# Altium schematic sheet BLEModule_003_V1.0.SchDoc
size 152 x 127 mm; SheetNumber: 0; SheetTotal: 0
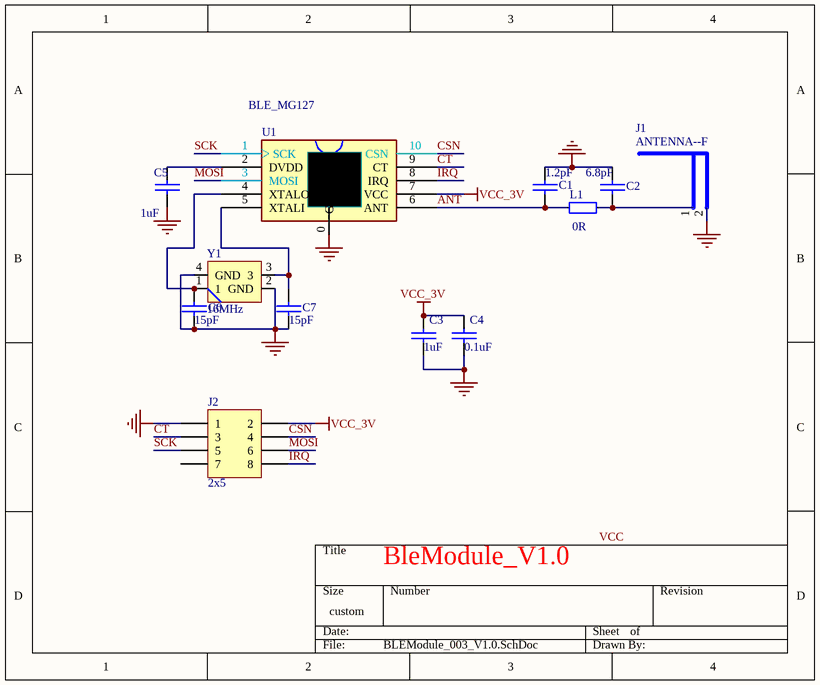
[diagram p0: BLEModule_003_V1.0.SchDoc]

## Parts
C1  1.2pF  [0402C]
C2  6.8pF  [0402C]
C3  1uF  [0402C]
C4  0.1uF  [0402C]
C5  1uF  [0402C]
C6  15pF  [0402C]
C7  15pF  [0402C]
J1  ANTENNA--F  [PIFA_LARGE]
J2  2x5  [HDR2X4]
L1  value 0R  [0402]  (hidden comment: 3.6nF)
U1  BLE_MG127  [DFN10]
Y1  16MHz  [XT3225]

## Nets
GND: C1.1 C2.1 C3.2 C4.2 C5.2 C6.2 C7.2 J1.2 J2.1 U1.0(GND) Y1.2(GND) Y1.4(GND)
VCC_3V: C3.1 C4.1 J2.2 U1.7(VCC)
ANT: C1.2 L1.2 U1.6(ANT)
CSN: J2.4 U1.10(CSN)
CT: J2.3 U1.9(CT)
IRQ: J2.8 U1.8(IRQ)
MOSI: J2.6 U1.3(MOSI)
SCK: J2.5 U1.1(SCK)
NetC2_2: C2.2 J1.1 L1.1
NetC5_1: C5.1 U1.2(DVDD)
NetC6_1: C6.1 U1.4(XTALO) Y1.1
NetC7_1: C7.1 U1.5(XTALI) Y1.3

Not connected (* = marked no-connect by the designer): J2 7

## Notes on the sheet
- BleModule_V1.0
- Labels drawn without touching a wire or pin: VCC

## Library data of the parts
C1-C7 = CAP: Capacitor
J1 = ANT
J2 = Header 4X2: Header, 4-Pin, Dual row
L1 = Res2: Resistor
Y1 = XTAL3225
